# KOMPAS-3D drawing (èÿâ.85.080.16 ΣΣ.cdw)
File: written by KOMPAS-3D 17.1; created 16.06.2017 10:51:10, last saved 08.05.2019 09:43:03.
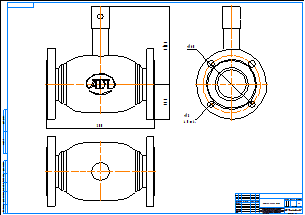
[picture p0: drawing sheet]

Sheet 1: A1, landscape

Title block, sheet 1: name: КШГ.85.080.16 фф; material: Внимание! Данный продукт является объектом авторского права ООО «Торговый Дом АДЛ». / Запрещается изменение, копирование, распространение / (в том числе путем копирования на другие сайты и ресурсы в Интернете) / или любое иное использование информации и объектов без предварительного / согласия правообладателя (ООО «Торговый Дом АДЛ»).; scale: 1:1; sheets: 1; organisation: ООО "Торговый дом АДЛ"; sheet format: A1; stored path: C:\Users\tra\Desktop\2д чертежи\Шаровые краны БИВАЛ\КШ_Бивал_серия_82_85\KOMPAS 2D\КШГ.85.080.16 фф.cdw

Views: Спереди 1, Проекционный вид 2, Проекционный вид 3
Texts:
  Klimkovich
  ADL
Dimensions and other numbers on the sheet: 300; 214,6; 97,5; 160; 18; 4 Отв.; 1:1; 1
